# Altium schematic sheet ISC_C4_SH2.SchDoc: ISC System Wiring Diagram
size C; DrawnBy: Filiberto Clara; Engineer: Filiberto Clara; Organization: LIGO Laboratory; Address1: California Institute of Technology; Address2: Massachusetts Institute of Technology; SheetNumber: 9; SheetTotal: 39
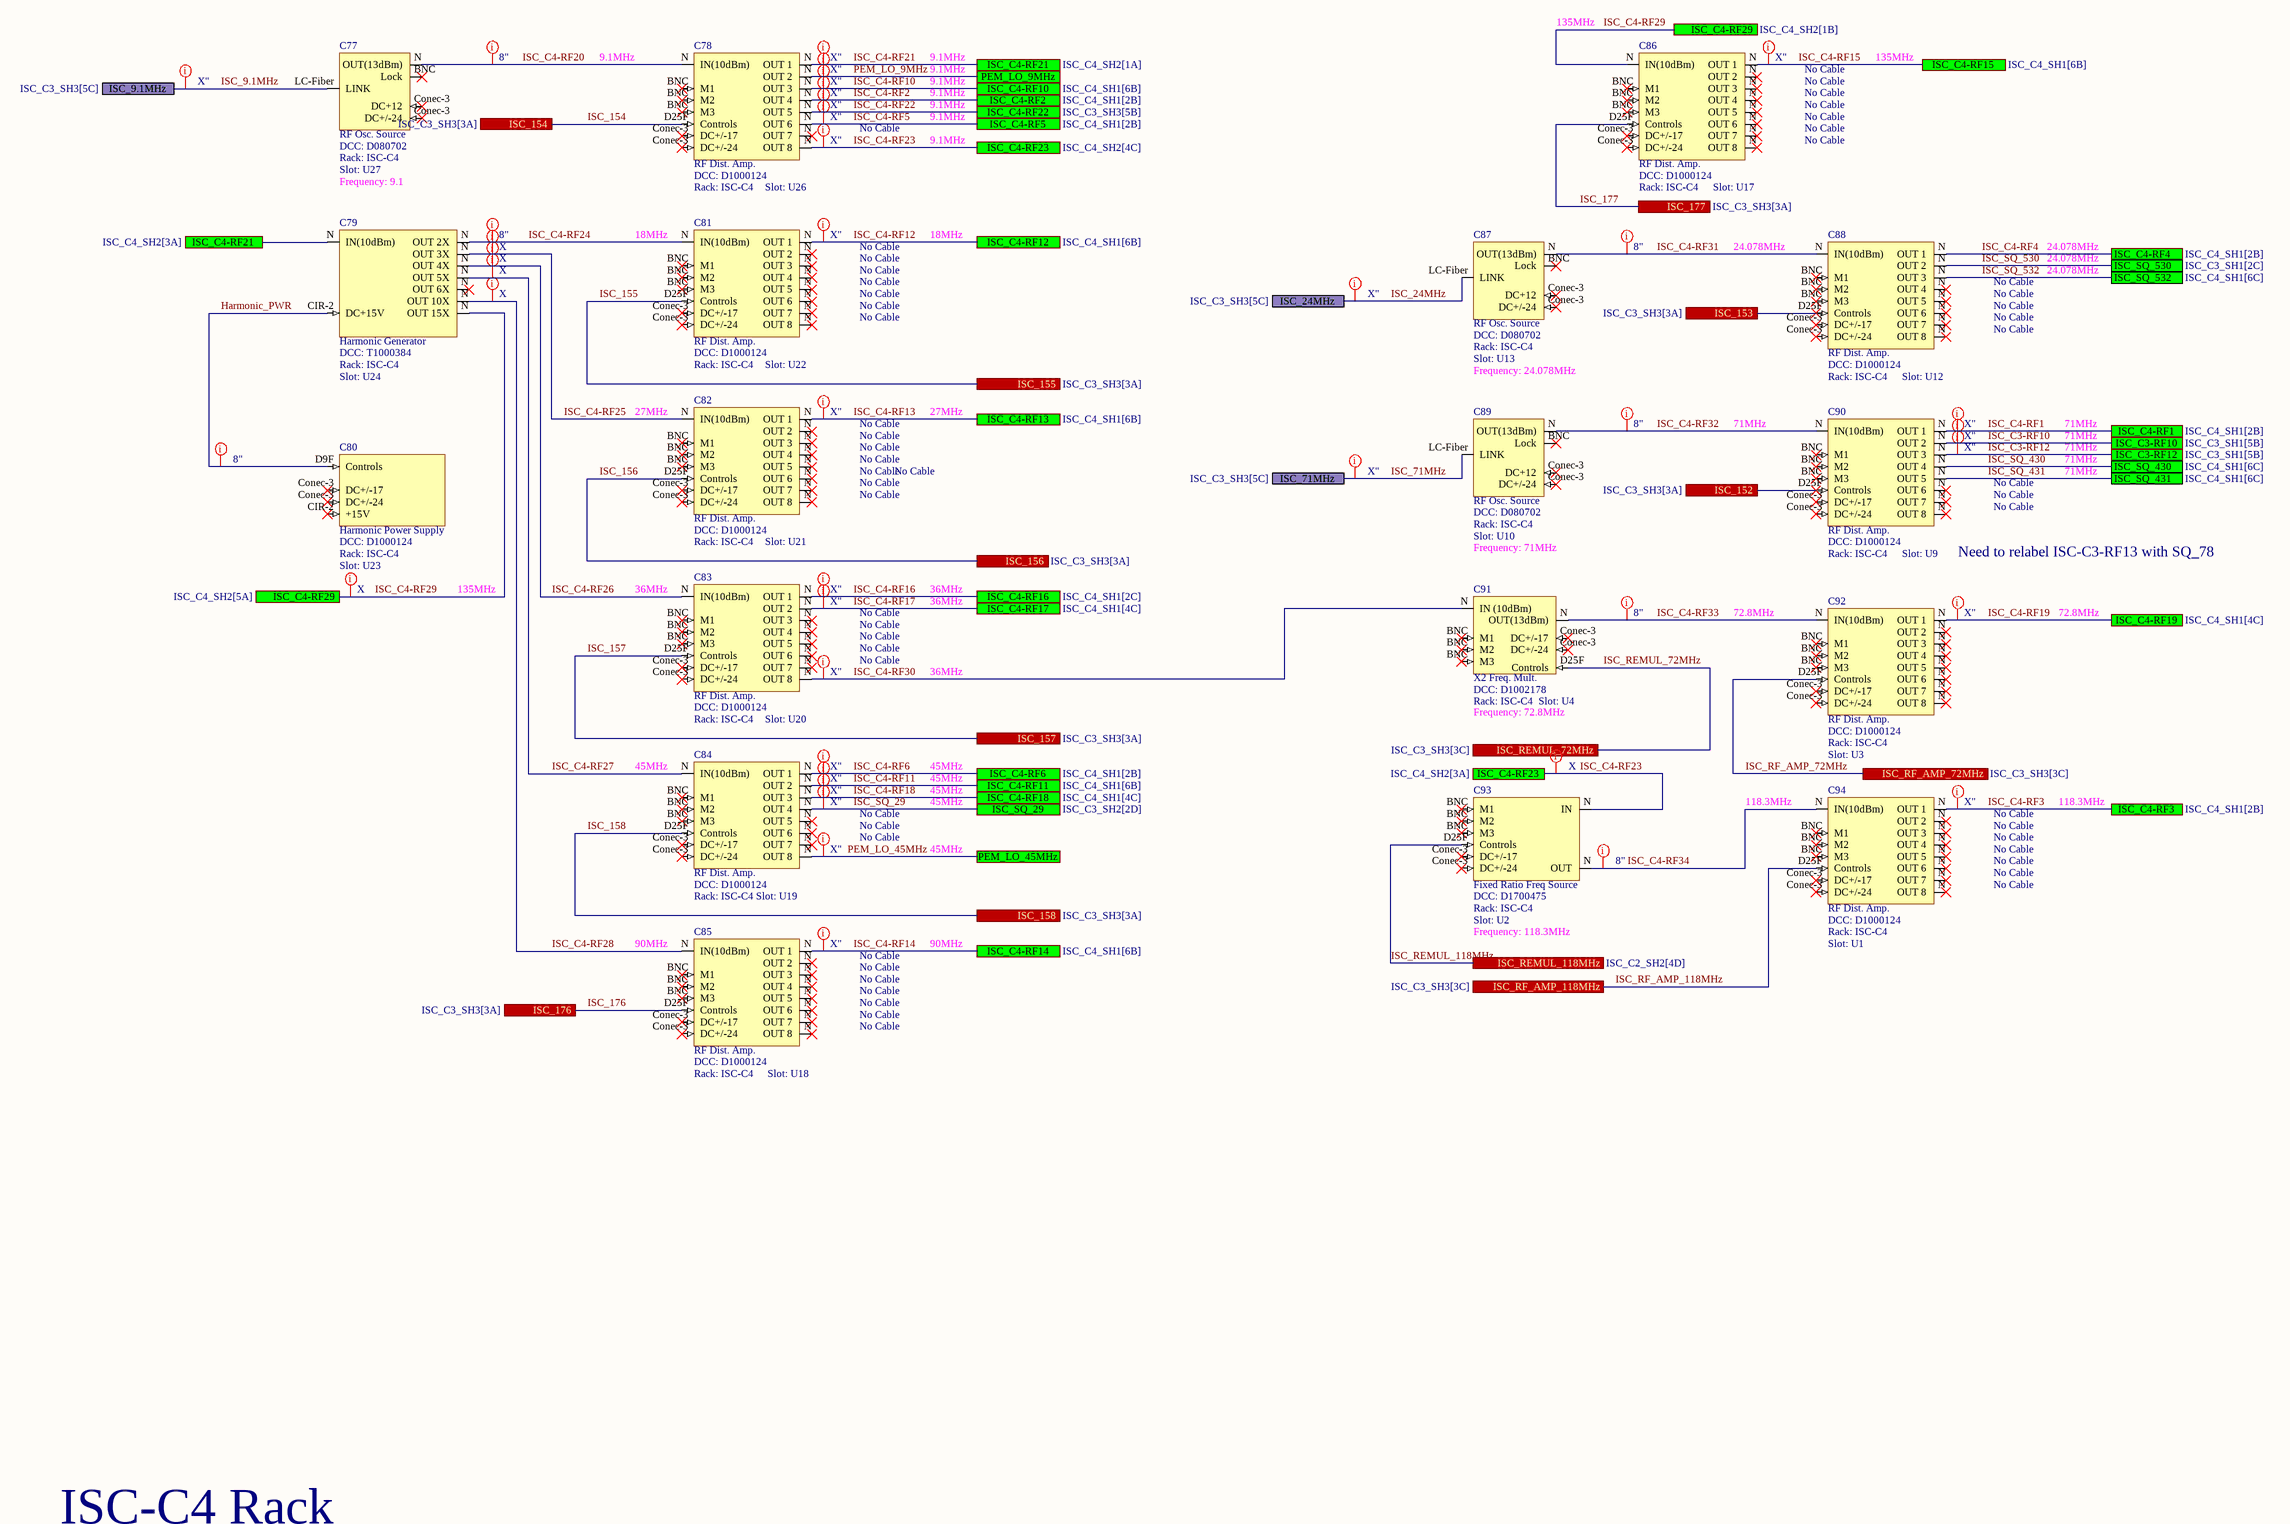
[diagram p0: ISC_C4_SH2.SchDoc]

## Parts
C77  RF Osc. Source  DCC: D080702  Rack: ISC-C4  Slot: U27  Frequency: 9.1
C78  RF Dist. Amp.  DCC: D1000124  Rack: ISC-C4  Slot: U26
C79  Harmonic Generator  DCC: T1000384  Rack: ISC-C4  Slot: U24
C80  Harmonic Power Supply  DCC: D1000124  Rack: ISC-C4  Slot: U23
C81  RF Dist. Amp.  DCC: D1000124  Rack: ISC-C4  Slot: U22
C82  RF Dist. Amp.  DCC: D1000124  Rack: ISC-C4  Slot: U21
C83  RF Dist. Amp.  DCC: D1000124  Rack: ISC-C4  Slot: U20
C84  RF Dist. Amp.  DCC: D1000124  Rack: ISC-C4  Slot: U19
C85  RF Dist. Amp.  DCC: D1000124  Rack: ISC-C4  Slot: U18
C86  RF Dist. Amp.  DCC: D1000124  Rack: ISC-C4  Slot: U17
C87  RF Osc. Source  DCC: D080702  Rack: ISC-C4  Slot: U13  Frequency: 24.078MHz
C88  RF Dist. Amp.  DCC: D1000124  Rack: ISC-C4  Slot: U12
C89  RF Osc. Source  DCC: D080702  Rack: ISC-C4  Slot: U10  Frequency: 71MHz
C90  RF Dist. Amp.  DCC: D1000124  Rack: ISC-C4  Slot: U9
C91  X2 Freq. Mult.  DCC: D1002178  Rack: ISC-C4  Slot: U4  Frequency: 72.8MHz
C92  RF Dist. Amp.  DCC: D1000124  Rack: ISC-C4  Slot: U3
C93  Fixed Ratio Freq Source  DCC: D1700475  Rack: ISC-C4  Slot: U2  Frequency: 118.3MHz
C94  RF Dist. Amp.  DCC: D1000124  Rack: ISC-C4  Slot: U1

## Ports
ISC_9.1MHz (see ISC_C3_SH3[5C]), ISC_24MHz (see ISC_C3_SH3[5C]), ISC_71MHz (see ISC_C3_SH3[5C]), ISC_152 (see ISC_C3_SH3[3A]), ISC_153 (see ISC_C3_SH3[3A]), ISC_154 (see ISC_C3_SH3[3A]), ISC_155 (see ISC_C3_SH3[3A]), ISC_156 (see ISC_C3_SH3[3A]), ISC_157 (see ISC_C3_SH3[3A]), ISC_158 (see ISC_C3_SH3[3A]), ISC_176 (see ISC_C3_SH3[3A]), ISC_177 (see ISC_C3_SH3[3A]), ISC_C3-RF10 (see ISC_C3_SH1[5B]), ISC_C3-RF12 (see ISC_C3_SH1[5B]), ISC_C4-RF1 (see ISC_C4_SH1[2B]), ISC_C4-RF2 (see ISC_C4_SH1[2B]), ISC_C4-RF3 (see ISC_C4_SH1[2B]), ISC_C4-RF4 (see ISC_C4_SH1[2B]), ISC_C4-RF5 (see ISC_C4_SH1[2B]), ISC_C4-RF6 (see ISC_C4_SH1[2B]), ISC_C4-RF10 (see ISC_C4_SH1[6B]), ISC_C4-RF11 (see ISC_C4_SH1[6B]), ISC_C4-RF12 (see ISC_C4_SH1[6B]), ISC_C4-RF13 (see ISC_C4_SH1[6B]), ISC_C4-RF14 (see ISC_C4_SH1[6B]), ISC_C4-RF15 (see ISC_C4_SH1[6B]), ISC_C4-RF16 (see ISC_C4_SH1[2C]), ISC_C4-RF17 (see ISC_C4_SH1[4C]), ISC_C4-RF18 (see ISC_C4_SH1[4C]), ISC_C4-RF19 (see ISC_C4_SH1[4C]), ISC_C4-RF21 (see ISC_C4_SH2[1A]), ISC_C4-RF21 (see ISC_C4_SH2[3A]), ISC_C4-RF22 (see ISC_C3_SH3[5B]), ISC_C4-RF23 (see ISC_C4_SH2[3A]), ISC_C4-RF23 (see ISC_C4_SH2[4C]), ISC_C4-RF29 (see ISC_C4_SH2[1B]), ISC_C4-RF29 (see ISC_C4_SH2[5A]), ISC_REMUL_72MHz (see ISC_C3_SH3[3C]), ISC_REMUL_118MHz (see ISC_C2_SH2[4D]), ISC_RF_AMP_72MHz (see ISC_C3_SH3[3C]), ISC_RF_AMP_118MHz (see ISC_C3_SH3[3C]), ISC_SQ_29 (see ISC_C3_SH2[2D]), ISC_SQ_430 (see ISC_C4_SH1[6C]), ISC_SQ_431 (see ISC_C4_SH1[6C]), ISC_SQ_530 (see ISC_C3_SH1[2C]), ISC_SQ_532 (see ISC_C4_SH1[6C]), PEM_LO_9MHz, PEM_LO_45MHz

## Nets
Harmonic_PWR: C79.CIR-2(DC+15V) C80.D9F(Controls)
ISC_9.1MHz: C77.LC-Fiber(LINK) ; port ISC_9.1MHz
ISC_24MHz: C87.LC-Fiber(LINK) ; port ISC_24MHz
ISC_71MHz: C89.LC-Fiber(LINK) ; port ISC_71MHz
ISC_152: C90.D25F(Controls) ; port ISC_152
ISC_153: C88.D25F(Controls) ; port ISC_153
ISC_154: C78.D25F(Controls) ; port ISC_154
ISC_155: C81.D25F(Controls) ; port ISC_155
ISC_156: C82.D25F(Controls) ; port ISC_156
ISC_157: C83.D25F(Controls) ; port ISC_157
ISC_158: C84.D25F(Controls) ; port ISC_158
ISC_176: C85.D25F(Controls) ; port ISC_176
ISC_177: C86.D25F(Controls) ; port ISC_177
ISC_C3-RF10: C90.N(OUT_2) ; port ISC_C3-RF10
ISC_C3-RF12: C90.N(OUT_3) ; port ISC_C3-RF12
ISC_C4-RF1: C90.N(OUT_1) ; port ISC_C4-RF1
ISC_C4-RF2: C78.N(OUT_4) ; port ISC_C4-RF2
ISC_C4-RF3: C94.N(OUT_1) ; port ISC_C4-RF3
ISC_C4-RF4: C88.N(OUT_1) ; port ISC_C4-RF4
ISC_C4-RF5: C78.N(OUT_6) ; port ISC_C4-RF5
ISC_C4-RF6: C84.N(OUT_1) ; port ISC_C4-RF6
ISC_C4-RF10: C78.N(OUT_3) ; port ISC_C4-RF10
ISC_C4-RF11: C84.N(OUT_2) ; port ISC_C4-RF11
ISC_C4-RF12: C81.N(OUT_1) ; port ISC_C4-RF12
ISC_C4-RF13: C82.N(OUT_1) ; port ISC_C4-RF13
ISC_C4-RF14: C85.N(OUT_1) ; port ISC_C4-RF14
ISC_C4-RF15: C86.N(OUT_1) ; port ISC_C4-RF15
ISC_C4-RF16: C83.N(OUT_1) ; port ISC_C4-RF16
ISC_C4-RF17: C83.N(OUT_2) ; port ISC_C4-RF17
ISC_C4-RF18: C84.N(OUT_3) ; port ISC_C4-RF18
ISC_C4-RF19: C92.N(OUT_1) ; port ISC_C4-RF19
ISC_C4-RF20: C77.N(OUT(13dBm)) C78.N(IN(10dBm))
ISC_C4-RF21: C78.N(OUT_1) C79.N(IN(10dBm)) ; port ISC_C4-RF21
ISC_C4-RF22: C78.N(OUT_5) ; port ISC_C4-RF22
ISC_C4-RF23: C78.N(OUT_8) C93.N(IN) ; port ISC_C4-RF23
ISC_C4-RF24: C79.N(OUT_2X) C81.N(IN(10dBm))
ISC_C4-RF25: C79.N(OUT_3X) C82.N(IN(10dBm))
ISC_C4-RF26: C79.N(OUT_4X) C83.N(IN(10dBm))
ISC_C4-RF27: C79.N(OUT_5X) C84.N(IN(10dBm))
ISC_C4-RF28: C79.N(OUT_10X) C85.N(IN(10dBm))
ISC_C4-RF29: C79.N(OUT_15X) C86.N(IN(10dBm)) ; port ISC_C4-RF29
ISC_C4-RF30: C83.N(OUT_8) C91.N(IN_(10dBm))
ISC_C4-RF31: C87.N(OUT(13dBm)) C88.N(IN(10dBm))
ISC_C4-RF32: C89.N(OUT(13dBm)) C90.N(IN(10dBm))
ISC_C4-RF33: C91.N(OUT(13dBm)) C92.N(IN(10dBm))
ISC_C4-RF34: C93.N(OUT) C94.N(IN(10dBm))
ISC_REMUL_72MHz: C91.D25F(Controls) ; port ISC_REMUL_72MHz
ISC_REMUL_118MHz: C93.D25F(Controls) ; port ISC_REMUL_118MHz
ISC_RF_AMP_72MHz: C92.D25F(Controls) ; port ISC_RF_AMP_72MHz
ISC_RF_AMP_118MHz: C94.D25F(Controls) ; port ISC_RF_AMP_118MHz
ISC_SQ_29: C84.N(OUT_4) ; port ISC_SQ_29
ISC_SQ_430: C90.N(OUT_4) ; port ISC_SQ_430
ISC_SQ_431: C90.N(OUT_5) ; port ISC_SQ_431
ISC_SQ_530: C88.N(OUT_2) ; port ISC_SQ_530
ISC_SQ_532: C88.N(OUT_3) ; port ISC_SQ_532
PEM_LO_9MHz: C78.N(OUT_2) ; port PEM_LO_9MHz
PEM_LO_45MHz: C84.N(OUT_8) ; port PEM_LO_45MHz

Not connected (* = marked no-connect by the designer): C77 BNC(Lock)* Conec-3(DC+12)*; C78 BNC(M1)* Conec-3(DC+/-17)*; C80 CIR-2(+15V)* Conec-3(DC+/-17)*; C81 BNC(M1)* Conec-3(DC+/-17)*; C82 BNC(M1)* Conec-3(DC+/-17)*; C83 BNC(M1)* Conec-3(DC+/-17)*; C84 BNC(M1)* Conec-3(DC+/-17)*; C85 BNC(M1)* Conec-3(DC+/-17)*; C86 BNC(M1)* Conec-3(DC+/-17)*; C87 BNC(Lock)* Conec-3(DC+12)*; C88 BNC(M1)* Conec-3(DC+/-17)*; C89 BNC(Lock)* Conec-3(DC+12)*; C90 BNC(M1)* Conec-3(DC+/-17)*; C91 BNC(M1)* Conec-3(DC+/-17)*; C92 BNC(M1)* Conec-3(DC+/-17)*; C93 BNC(M1)* Conec-3(DC+/-17)*; C94 BNC(M1)* Conec-3(DC+/-17)*

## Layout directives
Length: 8": Harmonic_PWR, ISC_C4-RF20, ISC_C4-RF24, ISC_C4-RF31, ISC_C4-RF32, ISC_C4-RF33, ISC_C4-RF34
Length: X": ISC_9.1MHz, ISC_24MHz, ISC_71MHz, ISC_C3-RF10, ISC_C3-RF12, ISC_C4-RF1, ISC_C4-RF2, ISC_C4-RF3, ISC_C4-RF5, ISC_C4-RF6, ISC_C4-RF10, ISC_C4-RF11, ISC_C4-RF12, ISC_C4-RF13, ISC_C4-RF14, ISC_C4-RF15, ISC_C4-RF16, ISC_C4-RF17, ISC_C4-RF18, ISC_C4-RF19, ISC_C4-RF21, ISC_C4-RF22, ISC_C4-RF23, ISC_C4-RF30, ISC_SQ_29, PEM_LO_9MHz, PEM_LO_45MHz
Length: X: ISC_C4-RF23, ISC_C4-RF25, ISC_C4-RF26, ISC_C4-RF27, ISC_C4-RF28, ISC_C4-RF29

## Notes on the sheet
- 9.1MHz
- 135MHz
- No Cable
- (near C81) 18MHz
- 18MHz
- (near C88) 24.078MHz
- 24.078MHz
- (near C82) 27MHz
- 27MHz
- 71MHz
- (near C83) 36MHz
- 36MHz
- (near C90) Need to relabel ISC-C3-RF13 with SQ_78
- 72.8MHz
- (near C84) 45MHz
- 45MHz
- (near C94) 118.3MHz
- 118.3MHz
- (near C85) 90MHz
- 90MHz
- ISC-C4 Rack

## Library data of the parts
C77 C87 C89 = RF Osc. Source: Serial: Sxxxxxxx; System: ISC
C78 C81-C86 C88 C90 C92 C94 = RF Distribution Amplifier: Serial: Sxxxxxxx; System: ISC
C79 = Harmonic Generator: Serial: Sxxxxxxx; System: ISC
C80 = Harmonic Power Supply: Serial: Sxxxxxxx; System: ISC
C91 = X2 Freq. Mult.: Serial: Sxxxxxxx; System: ISC
C93 = Fixed Ratio Freq Source: Serial: Sxxxxxxx; System: ISC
